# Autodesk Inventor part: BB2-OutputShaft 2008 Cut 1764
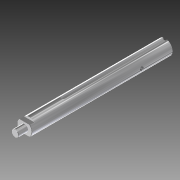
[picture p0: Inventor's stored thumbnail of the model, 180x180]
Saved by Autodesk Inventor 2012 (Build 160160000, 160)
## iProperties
Company: FirstCadLibrary
Shininess: 64.0
Length Units: 11269
Angle Units: 11279
Time Units: 11290
Mass Units: 11283
Length Display Precision: 3
Angle Display Precision: 2
Compacted: True
Part Number: BB2-OutputShaft 2008 Cut 1764
Document SubType Name: Modeling
Created: 2007-01
Material: Steel, Mild
Designer: Ed Sparks
Catalog Web Link: www.banebots.com
Vendor: BaneBots
Mass: 120.202 g
Surface Area: 60.1384 cm^2
Volume: 15.2928 cm^3
Density: 7.86 g/cm^3
Density: 0.0
Volumn: 0.0
Area: 0.0
PropertySet Name: Model Information
Control State: 0
Master: False
Checked Out: False
Author: Ed Sparks
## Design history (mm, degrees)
sketch "Sketch1"
  geometry: C1 r 6.35 at (0, 0); 1 further point
  constraints: 1 centre point, 1 coincident, 1 other
  dimensions: "d0" = 12.7 diameter of C1
extrude "Extrusion1" new body sketch "Sketch1" stored distance "d1" = 127; taper "d2" = 0 deg
sketch "Sketch2"
  geometry: L1 (-4.5, 4.48)-(-4.5, -4.48); L2 (4.5, 4.48)-(4.5, -4.48); L3 (0, 0)-(0, 6.178); A1 r 6.35 centre (0, 0) between (-4.5, -4.48) and (4.5, 4.48) reference
  constraints: 6 end point, 4 point on circle, 2 vertical, 1 parallel, 1 other
  dimensions: "d3" = 9 distance between parallel lines of L2 L1
extrude "Extrusion2" cut sketch "Sketch2" distance "d4" = 4; taper "d5" = 0 deg
sketch "Sketch3"
  geometry: C1 r 3 at (0, 0); A1 r 6.35 centre (0, 0) between (4.5, 4.48) and (-4.5, 4.48) reference
  constraints: 1 centre point, 1 coincident, 1 concentric
  dimensions: "d6" = 6 diameter of C1
extrude "Extrusion3" join sketch "Sketch3" distance "d7" = 8.2; taper "d8" = 0 deg
chamfer "Chamfer1" distance "d9" = 0.25; stored, may be unused: second distance "d10" = 2, angle "d17" = 45 deg
workplane "Work Plane1"
sketch "Sketch4"
  geometry: L1 (6.1, -63.5)-(-6.1, -63.5) reference; L2 (0, -63.5)-(0, -7.87); L3 (-1.588, -63.5)-(-1.587, 30.163); L4 (0, 31.75)-(0, 31.75); L5 (1.587, 30.163)-(1.588, -63.5); A1 r 1.587 centre (0, 30.163) between (0, 31.75) and (-1.587, 30.163); A2 r 1.587 centre (0, 30.163) between (1.587, 30.163) and (0, 31.75); 1 further point
  constraints: 8 end point, 4 point on circle, 4 point on line, 4 tangent, 3 perpendicular, 2 centre point, 1 concentric, 1 midpoint, 1 parallel, 1 other
  dimensions: "d12" = 95.25 distance of point (1.587, 31.75) L5.end; "d13" = 3.175 distance between parallel lines of L5 L3; "d14" = 1.5875 radius of A1
extrude "Extrusion4" cut sketch "Sketch4" distance "d15" = 1.5875; taper "d16" = 0 deg
sketch "Sketch5"
  geometry: C1 r 3.175 at (0, 0); A1 r 6.1 centre (0, 0) between (-5.89, -1.588) and (-5.89, 1.588) reference
  constraints: 1 centre point, 1 coincident
  dimensions: "d18" = 6.35 diameter of C1
extrude "Extrusion5" cut sketch "Sketch5" distance "d19" = 15; taper "d20" = 0 deg
thread "Thread1" dims "d21" = 10, "d22" = 0
sketch "Sketch6"
  geometry: C1 r 3.175 at (0, 0) reference; C2 r 6.35 at (0, 0); A1 r 6.35 centre (0, 0) between (-6.148, -1.588) and (-6.148, 1.588) reference
  constraints: 1 centre point, 1 coincident, 1 concentric
extrude "Extrusion8" cut sketch "Sketch6" distance "d28" = 17.399; taper "d29" = 0 deg
sketch "Sketch8"
  geometry: L1 (6.35, -46.101)-(-6.148, -46.101) reference; C1 r 1.587 at (-0.086, -31.496)
  constraints: 1 centre point
  dimensions: "d30" = 3.175 diameter of C1; "d42" = 14.605 distance from line of L1 C1.centre
extrude "Extrusion9" cut sketch "Sketch8" distance "d31" = 100; taper "d32" = 0 deg
sketch "Sketch9"
  geometry: C1 r 3.224 at (0, 0); A1 r 6.35 centre (0, 0) between (-6.148, -1.588) and (-6.148, 1.587) reference
  constraints: 1 centre point, 1 coincident
  dimensions: "d33" = 6.447 diameter of C1
extrude "Extrusion10" cut sketch "Sketch9" distance "d34" = 20.955; taper "d35" = 0 deg
thread "Thread2" dims "d36" = 10, "d37" = 0
sketch "Sketch10"
  geometry: L1 (-6.148, -1.588)-(-4.763, -1.588) reference; L2 (-4.763, 1.587)-(-6.148, 1.587) reference; L3 (-4.763, -1.588)-(-4.763, 1.587) reference; C1 r 3.224 at (0, 0) reference; C2 r 6.35 at (0, 0); A1 r 6.35 centre (0, 0) between (-6.148, -1.588) and (-6.148, 1.587) reference
  constraints: 1 centre point, 1 coincident, 1 concentric
extrude "Extrusion11" cut sketch "Sketch10" distance "d38" = 3.3782; taper "d39" = 0 deg
sketch "Sketch11"
  geometry: L1 (-6.148, -1.588)-(-4.763, -1.588) reference; L2 (-6.148, 1.587)-(-4.763, 1.587); L3 (-4.763, 1.587)-(-4.763, -1.588); L4 (-6.148, -1.588)-(-4.763, -1.588); C1 r 3.224 at (0, 0) reference; C2 r 3.224 at (0, 0); A1 r 6.35 centre (0, 0) between (-6.148, -1.588) and (-6.148, 1.587) reference; A2 r 6.35 centre (0, 0) between (-6.148, -1.588) and (-6.148, 1.587)
  constraints: 6 end point, 2 centre point, 2 concentric, 2 equal length, 2 point on circle, 1 coincident, 1 perpendicular
extrude "Extrusion12" join sketch "Sketch11" distance "d40" = 0.762; taper "d41" = 0 deg
sketch "Sketch12"
  geometry: L1 (-6.148, -1.588)-(-4.763, -1.588) reference; L2 (-4.763, 1.587)-(-6.148, 1.587) reference; L3 (-4.763, -1.588)-(-4.763, 1.587) reference; L4 (-6.148, -1.588)-(-4.763, -1.588); L5 (-4.763, 1.587)-(-4.763, -1.588); L6 (-4.763, 1.587)-(-6.148, 1.587); C1 r 3.224 at (0, 0) reference; A1 r 6.35 centre (0, 0) between (-6.148, -1.588) and (-6.148, 1.587) reference; A2 r 6.35 centre (0, 0) between (-6.148, -1.588) and (-6.148, 1.587)
  constraints: 6 end point, 2 collinear, 2 point on circle, 1 centre point, 1 concentric, 1 perpendicular
extrude "Extrusion13" cut sketch "Sketch12" distance "d43" = 4.445; taper "d44" = 0 deg
sketch "Sketch13"
  geometry: L1 (-4.763, 1.587)-(-6.148, 1.587) reference; L2 (-4.763, -1.588)-(-4.763, 1.587) reference; L3 (-6.148, -1.588)-(-4.763, -1.588) reference; C1 r 3.224 at (0, 0) reference; A1 r 6.35 centre (0, 0) between (-6.148, -1.588) and (-6.148, 1.587) reference
extrude "Extrusion14" join sketch "Sketch13" distance "d45" = 19.05; taper "d46" = 0 deg
body "Solid1"
other parameters: "d11" = 6.35
